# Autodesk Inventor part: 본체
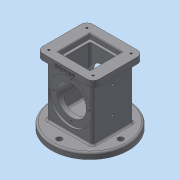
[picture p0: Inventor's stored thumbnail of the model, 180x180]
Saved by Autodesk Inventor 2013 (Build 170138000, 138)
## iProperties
Created: 2018-10
Part Number: 본체
Material: 일반
Document SubType Name: Modeling
Designer: dgall
Density: 1 g/cm^3
Author: dgall
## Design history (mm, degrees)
sketch "스케치1"
  geometry: L1 (-37, 33)-(37, 33); L2 (37, 33)-(37, -33); L3 (37, -33)-(-37, -33); L4 (-37, -33)-(-37, 33); 3 further points
  constraints: 8 end point, 2 midpoint, 2 parallel, 1 horizontal, 1 horizontal alignment, 1 perpendicular, 1 vertical alignment
  dimensions: "d0" = 74 distance of L1.start L1.end; "d2" = 66 distance of L1.end L2.end
extrude "돌출1" new body sketch "스케치1" stored distance "d3" = 88; taper "d4" = 0 deg
sketch "스케치2"
  geometry: L1 (-46, 41)-(46, 41); L2 (46, 41)-(46, -41); L3 (46, -41)-(-46, -41); L4 (-46, -41)-(-46, 41); 3 further points
  constraints: 8 end point, 2 midpoint, 2 parallel, 1 horizontal, 1 horizontal alignment, 1 perpendicular, 1 vertical alignment
  dimensions: "d5" = 82 distance of L1.end L2.end; "d7" = 92 distance of L1.start L1.end
extrude "돌출2" join sketch "스케치2" distance "d8" = 10; taper "d9" = 0 deg
sketch "스케치3"
  geometry: L1 (-26, 26)-(26, 26); L2 (26, 26)-(26, -26); L3 (26, -26)-(-26, -26); L4 (-26, -26)-(-26, 26); 3 further points
  constraints: 8 end point, 2 midpoint, 2 parallel, 2 perpendicular, 1 horizontal, 1 horizontal alignment, 1 vertical alignment
  dimensions: "d10" = 52 distance of L1.start L1.end
extrude "돌출3" cut sketch "스케치3" distance "d12" = 8; taper "d13" = 0 deg
sketch "스케치4"
  geometry: L1 (-22, 22)-(22, 22); L2 (22, 22)-(22, -22); L3 (22, -22)-(-22, -22); L4 (-22, -22)-(-22, 22); 3 further points
  constraints: 8 end point, 2 midpoint, 2 parallel, 2 perpendicular, 1 horizontal, 1 horizontal alignment, 1 vertical alignment
  dimensions: "d14" = 44 distance of L1.start L1.end
extrude "돌출4" cut sketch "스케치4" distance "d16" = 74; taper "d17" = 0 deg
fillet "모깎기2" dims "d80" = 3
fillet "모깎기3" dims "d81" = 3
node "작업 평면1"
sketch "스케치5"
  geometry: C1 r 62.5 at (0, 0); 1 further point
  constraints: 1 centre point, 1 coincident
  dimensions: "d19" = 125 diameter of C1
extrude "돌출5" join sketch "스케치5" distance "d21" = 10; taper "d22" = 0 deg
sketch "스케치6" dims "d23" = 100
  geometry: C1 r 62.5 at (0, 0) reference; 2 further points
  constraints: 2 vertical alignment, 1 coincident, 2 other
hole "구멍1" sketch "스케치6" at (0, 50) diameter "d25" = 9; stored, may be unused: countersink angle "d29" = 90 deg, drill point angle "d31" = 118 deg; dims "d26" = 6, "d27" = 4, "d28" = 2, "d30" = 8
sketch "스케치7"
  geometry: C1 r 35 at (37, -44); 1 further point
  constraints: 1 centre point, 1 coincident
  dimensions: "d35" = 70 diameter of C1
extrude "돌출6" cut sketch "스케치7" distance "d37" = 3; taper "d38" = 0 deg
hole "구멍2" diameter "d41" = 48; stored, may be unused: countersink angle "d45" = 90 deg, drill point angle "d47" = 118 deg; dims "d39" = 10, "d40" = 10, "d42" = 6, "d43" = 4, "d44" = 2, "d46" = 8
sketch "스케치8" dims "d48" = 58
  geometry: C1 r 24 at (0, 0) reference; C2 r 35 at (0, 0) reference; 2 further points
  constraints: 2 vertical alignment, 1 coincident, 2 other
hole "구멍3" sketch "스케치8" at (0, -29) diameter "d50" = 3.242; stored, may be unused: countersink angle "d54" = 82 deg, drill point angle "d56" = 118 deg; dims "d51" = 4, "d52" = 3.023, "d53" = 2, "d55" = 6
fillet "모깎기1" dims "d60" = 10
hole "구멍4" diameter "d63" = 3.242; stored, may be unused: countersink angle "d67" = 82 deg, drill point angle "d69" = 118 deg; dims "d61" = 10, "d62" = 10, "d64" = 4, "d65" = 3.023, "d66" = 2, "d68" = 6
sketch "스케치9"
  geometry: L1 (98, -29.5)-(98, 95.5) reference; L2 (98, 37.5)-(98, 28.5) reference; L3 (98, 33)-(61, 33); L4 (61, 33)-(18, 33); 3 further points
  constraints: 4 end point, 2 coincident, 1 collinear, 1 midpoint, 1 perpendicular
  dimensions: "d70" = 37 distance of L3.start L3.end; "d72" = 43 distance of L3.end L4.end
hole "구멍5" sketch "스케치9" at (61, 33), (18, 33) diameter "d73" = 4.134; stored, may be unused: countersink angle "d77" = 82 deg, drill point angle "d79" = 118 deg; dims "d74" = 4, "d75" = 3.023, "d76" = 2, "d78" = 20
fillet "모깎기4" dims "d82" = 3
fillet "모깎기5" dims "d83" = 3
node "작업 평면2"
sketch "스케치10"
  geometry: L1 (-62.5, -54)-(62.5, -54) reference; L2 (-28, -54)-(-24.826, -36); L3 (-24.826, -36)-(0, -36); L4 (0, -36)-(0, -54); 1 further point
  constraints: 6 end point, 1 midpoint, 1 parallel, 1 point on line, 1 vertical alignment
  dimensions: "d85" = 18 distance between parallel lines of L1 L3; "d87" = 28 distance of L4.end L2.start; "d88" = 80 deg angle of L2 L1
revolve "회전1" sketch "스케치10" stored, may be unused: angle "d89" = 90 deg
fillet "모깎기6" dims "d90" = 3
chamfer "모따기1" distance "d91" = 1; stored, may be unused: second distance "d92" = 2, angle "d93" = 45 deg
sketch "스케치11"
  geometry: L1 (72, 0)-(0, 0) reference; L2 (-10, 10)-(-10, 0) reference; 2 further points
  constraints: 1 other
  dimensions: "d94" = 46 distance from line of L2 point (36, 4); "d95" = 4 distance from line of L1 point (36, 4)
feature "엠보싱1" sketch "스케치11" dims "d0" = 74, "d2" = 66, "d96" = 0.5, "d97" = 0
node "솔리드1"
pattern_circular "원형 패턴1" dims angle "d33" = 360 deg
mirror "대칭1"
pattern_circular "원형 패턴2" dims angle "d58" = 360 deg
mirror "대칭2"
mirror "대칭3"
mirror "대칭4"
other parameters: "d18" = -54, "d84" = 0
